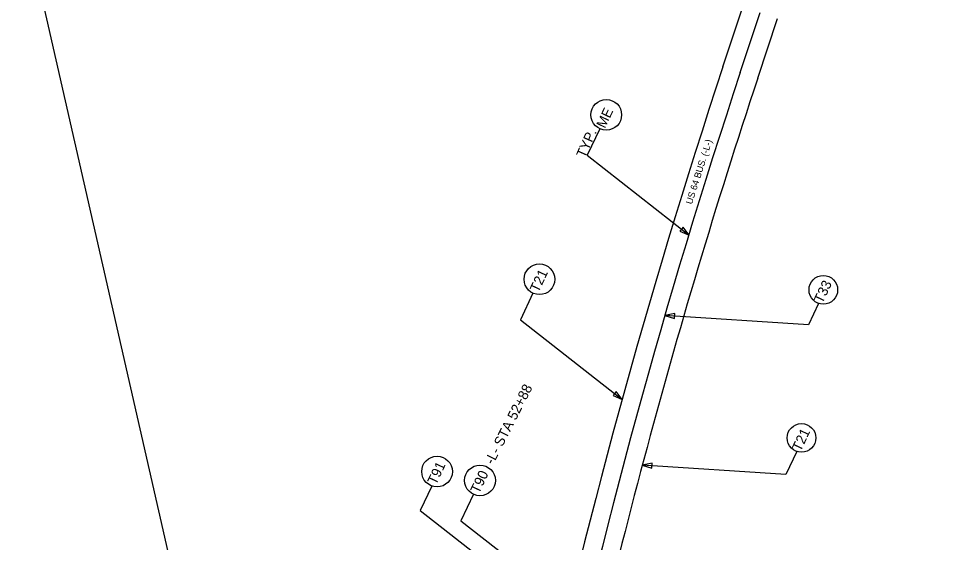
# Model space of a CAD drawing. Extents: x 553958 to 562499, y 493978 to 516388.
# Drawn here: x 556900 to 557453, y 505930 to 506244 of the extents above; entities that cross this region are included whole.
import ezdxf

# ---------------------------------------------------------------- set-up
doc = ezdxf.new("R2010")
doc.units = 0
for name, color, linetype in [('Default', 7, 'Continuous'), ('Prop Erosion Rip Rap Class II Label', 7, 'Continuous'), ('Raster_Level_0', 7, 'Continuous'), ('Sheet Plan CELL', 7, 'Continuous'), ('Sheet Plot Border Inside CELL', 7, 'Continuous')]:
    doc.layers.add(name, color=color, linetype=linetype)

msp = doc.modelspace()

# ---------------------------------------------------------------- linework, layer by layer
at = {"layer": 'Prop Erosion Rip Rap Class II Label'}
msp.add_lwpolyline([(557510.24, 505740.54), (557854.59, 506431.05), (557889.73, 506539.36), (557425.46, 506933.59), (557046.6, 506628.46), (556899.98, 506318.25), (557006.57, 505850.3)], close=True, dxfattribs=at)
at = {"layer": 'Raster_Level_0'}
msp.add_line((557333.73, 506211.9), (557345.67, 506247.87), dxfattribs=at)
msp.add_arc((561130.03, 504951.7), 4000, 161.63616, 173.98751, dxfattribs=at)
at = {"layer": 'Sheet Plan CELL'}
for points in [[(557249.26, 506178.17), (557241.72, 506162.22), (557302.93, 506114.3)], [(557209.1, 506079.44), (557201.56, 506063.49), (557262.77, 506015.57)], [(557380.74, 506073.26), (557374.75, 506060.47), (557288.4, 506066.1)], [(557367.64, 505984.39), (557361.16, 505970.55), (557274.8, 505976.18)], [(557148.39, 505963.62), (557141.4, 505948.88), (557226.34, 505882.38)], [(557173.37, 505958.65), (557165.84, 505942.7), (557227.05, 505894.79)]]:
    msp.add_lwpolyline(points, dxfattribs=at)
for points in [[(557297.41, 506116.65), (557302.93, 506114.3), (557299.32, 506119.1)], [(557294.28, 506067.27), (557288.4, 506066.1), (557294.08, 506064.18)], [(557257.25, 506017.92), (557262.77, 506015.57), (557259.17, 506020.37)], [(557280.69, 505977.35), (557274.8, 505976.18), (557280.48, 505974.25)]]:
    msp.add_lwpolyline(points, close=True, dxfattribs=at)
for centre, radius in [((557253.19, 506186.5), 9.22), ((557213.04, 506087.77), 9.22), ((557383.6, 506081.43), 8.61), ((557370.48, 505992.52), 8.61), ((557151.51, 505972.29), 9.22), ((557177.31, 505966.98), 9.22)]:
    msp.add_circle(centre, radius, dxfattribs=at)
at = {"layer": 'Sheet Plot Border Inside CELL'}
for p, q in [((557323.29, 506215.37), (557335.23, 506251.34)), ((557344.17, 506208.44), (557356.11, 506244.41))]:
    msp.add_line(p, q, dxfattribs=at)
for radius, end in [(4011, 173.98751), (3989, 168.49878)]:
    msp.add_arc((561130.03, 504951.7), radius, 161.63616, end, dxfattribs=at)

# ---------------------------------------------------------------- texts
at = {"layer": 'Default'}
msp.add_text('US 64 BUS. (-L-)', height=4, rotation=72.5051, dxfattribs=at).set_placement((557304.68, 506132.46))
at = {"layer": 'Sheet Plan CELL'}
for s, rotation, p in [(' ME', 64.7021, (557251.43, 506175.99)), ('TYP.', 66.1348, (557240.41, 506160.17)), ('T21', 64.7021, (557212.4, 506079.41)), ('T33', 64.7021, (557383.04, 506072.81)), ('-L- STA 52+88', 63.0266, (557185.24, 505976.11)), ('T21', 64.7021, (557369.92, 505983.9)), ('T91', 64.7021, (557150.88, 505963.93)), ('T90', 64.7021, (557176.68, 505958.62))]:
    msp.add_text(s, height=6, rotation=rotation, dxfattribs=at).set_placement(p)

doc.saveas('drawing.dxf')
